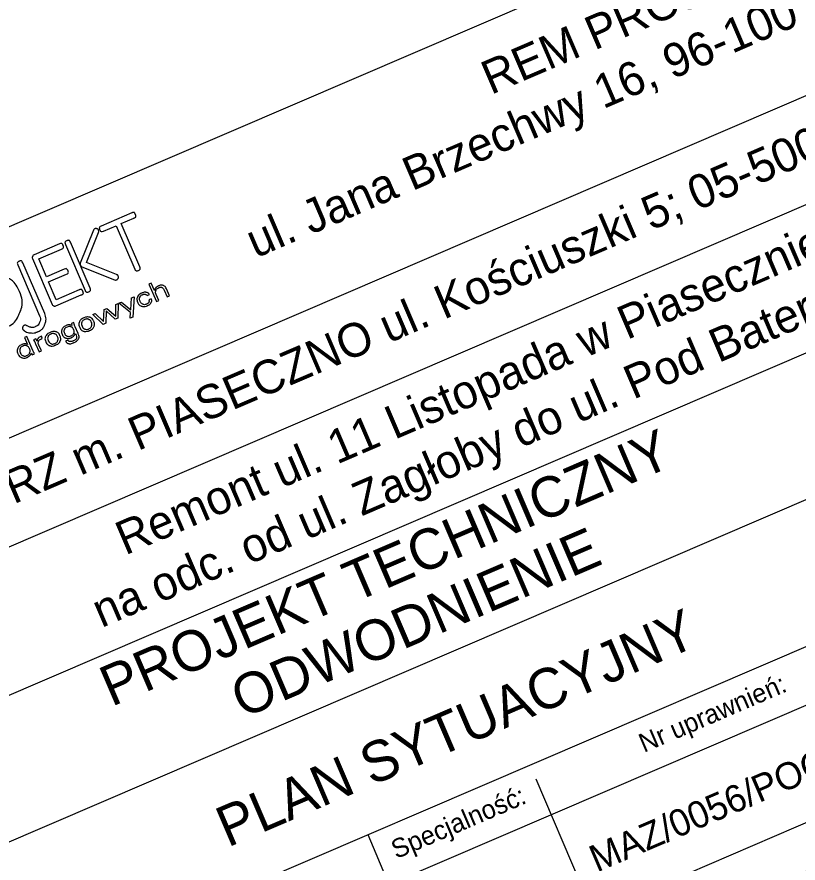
# Model space of a CAD drawing. Extents: x 7500108 to 7500715, y 5768804 to 5769157.
# Drawn here: x 7500613.89 to 7500642.87, y 5769014.08 to 5769045.44 of the extents above; entities that cross this region are included whole.
import ezdxf

# ---------------------------------------------------------------- set-up
doc = ezdxf.new("R2010")
doc.units = 0
doc.layers.add('KLASOUZYTKI', color=7, linetype='Continuous')

msp = doc.modelspace()

# ---------------------------------------------------------------- linework, layer by layer
at = {"layer": 'KLASOUZYTKI'}
for p, q in [((7500592.463, 5769020.775), (7500656.791, 5769048.376)), ((7500593.929, 5769017.358), (7500658.257, 5769044.959)), ((7500595.919, 5769012.719), (7500660.248, 5769040.32)), ((7500618.876, 5769035.575), (7500618.79, 5769035.538)), ((7500618.79, 5769035.538), (7500619.067, 5769034.893)), ((7500618.993, 5769035.302), (7500618.876, 5769035.575)), ((7500619.355, 5769035.316), (7500619.464, 5769035.063)), ((7500619.55, 5769035.1), (7500619.436, 5769035.365)), ((7500618.719, 5769035.115), (7500618.808, 5769035.154)), ((7500618.877, 5769034.993), (7500618.788, 5769034.955)), ((7500619.153, 5769034.93), (7500619.057, 5769035.154)), ((7500619.464, 5769035.063), (7500619.55, 5769035.1)), ((7500619.067, 5769034.893), (7500619.153, 5769034.93)), ((7500614.599, 5769033.509), (7500614.511, 5769033.471)), ((7500614.64, 5769033.427), (7500614.599, 5769033.509)), ((7500614.799, 5769033.607), (7500614.783, 5769033.6)), ((7500614.833, 5769033.528), (7500614.799, 5769033.607)), ((7500614.814, 5769033.52), (7500614.833, 5769033.528)), ((7500614.584, 5769033.321), (7500614.712, 5769033.024)), ((7500614.799, 5769033.062), (7500614.708, 5769033.274)), ((7500614.712, 5769033.024), (7500614.799, 5769033.062)), ((7500597.891, 5769008.124), (7500652.111, 5769031.388)), ((7500600.651, 5769001.691), (7500664.98, 5769029.292)), ((7500599.862, 5769003.529), (7500654.082, 5769026.793)), ((7500602.228, 5768998.015), (7500656.448, 5769021.279)), ((7500633.138, 5769017.202), (7500636.862, 5769008.522)), ((7500626.905, 5769015.132), (7500630.848, 5769005.942))]:
    msp.add_line(p, q, dxfattribs=at)
msp.add_lwpolyline([(7500603.806, 5768994.339), (7500668.134, 5769021.941), (7500653.956, 5769054.985), (7500589.627, 5769027.383)], close=True, dxfattribs=at)
for points in [[(7500618.152, 5769038.176), (7500617.018, 5769037.689)], [(7500618.449, 5769036.177), (7500617.76, 5769037.783), (7500618.233, 5769037.986)], [(7500616.728, 5769037.531), (7500616.243, 5769036.316)], [(7500617.1, 5769037.5), (7500617.571, 5769037.702), (7500618.26, 5769036.097)], [(7500617.591, 5769035.888), (7500616.471, 5769036.336), (7500616.919, 5769037.455)], [(7500615.47, 5769037.025), (7500614.526, 5769036.62)], [(7500615.689, 5769037.007), (7500616.419, 5769035.306)], [(7500616.607, 5769035.387), (7500615.877, 5769037.088)], [(7500615.647, 5769036.093), (7500614.985, 5769035.809), (7500614.701, 5769036.471), (7500615.551, 5769036.835)], [(7500613.922, 5769036.249), (7500614.732, 5769034.361)], [(7500614.921, 5769034.442), (7500614.111, 5769036.33)], [(7500614.472, 5769036.484), (7500615.201, 5769034.784)], [(7500615.35, 5769034.958), (7500615.066, 5769035.62), (7500615.728, 5769035.904)], [(7500616.3, 5769036.182), (7500617.515, 5769035.697)], [(7500616.201, 5769035.322), (7500615.35, 5769034.958)], [(7500615.337, 5769034.73), (7500616.28, 5769035.134)], [(7500618.185, 5769034.313), (7500618.091, 5769034.273), (7500618.105, 5769034.483), (7500617.674, 5769034.828), (7500617.775, 5769034.871), (7500618.118, 5769034.587), (7500618.145, 5769035.03), (7500618.239, 5769035.07), (7500618.185, 5769034.313)], [(7500617.539, 5769034.237), (7500617.199, 5769034.544), (7500617.185, 5769034.086), (7500617.093, 5769034.046), (7500616.702, 5769034.411), (7500616.793, 5769034.45), (7500617.106, 5769034.152), (7500617.123, 5769034.592), (7500617.228, 5769034.636), (7500617.555, 5769034.344), (7500617.565, 5769034.781), (7500617.648, 5769034.817), (7500617.637, 5769034.28), (7500617.539, 5769034.237)], [(7500615.998, 5769034.109), (7500615.912, 5769034.072), (7500615.933, 5769034.005)], [(7500616.161, 5769033.708), (7500616.055, 5769033.955), (7500616.045, 5769033.977)], [(7500614.481, 5769033.078), (7500614.26, 5769033.594), (7500614.174, 5769033.558), (7500614.285, 5769033.301)], [(7500615.785, 5769033.463), (7500615.697, 5769033.425)], [(7500616.065, 5769033.701), (7500616.089, 5769033.645)], [(7500614.421, 5769032.981), (7500614.457, 5769032.915), (7500614.544, 5769032.953)]]:
    msp.add_lwpolyline(points, dxfattribs=at)
for points, degree in [([(7500618.286, 5769038.121), (7500618.259, 5769038.184), (7500618.214, 5769038.203), (7500618.152, 5769038.176)], 2), ([(7500618.233, 5769037.986), (7500618.296, 5769038.013), (7500618.313, 5769038.058), (7500618.286, 5769038.121)], 2), ([(7500616.919, 5769037.455), (7500616.93, 5769037.483), (7500616.93, 5769037.509), (7500616.92, 5769037.534), (7500616.92, 5769037.534), (7500616.909, 5769037.559), (7500616.889, 5769037.578), (7500616.861, 5769037.589), (7500616.861, 5769037.589), (7500616.833, 5769037.6), (7500616.806, 5769037.6), (7500616.78, 5769037.589), (7500616.78, 5769037.589), (7500616.756, 5769037.578), (7500616.739, 5769037.559), (7500616.728, 5769037.531)], 3), ([(7500617.018, 5769037.689), (7500616.955, 5769037.662), (7500616.937, 5769037.617), (7500616.964, 5769037.554), (7500616.964, 5769037.554), (7500616.991, 5769037.491), (7500617.036, 5769037.473), (7500617.1, 5769037.5)], 3), ([(7500615.877, 5769037.088), (7500615.85, 5769037.151), (7500615.805, 5769037.17), (7500615.743, 5769037.143), (7500615.743, 5769037.143), (7500615.68, 5769037.116), (7500615.662, 5769037.071), (7500615.689, 5769037.007)], 3), ([(7500615.551, 5769036.835), (7500615.615, 5769036.863), (7500615.633, 5769036.908), (7500615.605, 5769036.971), (7500615.605, 5769036.971), (7500615.578, 5769037.034), (7500615.533, 5769037.052), (7500615.47, 5769037.025)], 3), ([(7500614.526, 5769036.62), (7500614.5, 5769036.609), (7500614.482, 5769036.59), (7500614.471, 5769036.563), (7500614.471, 5769036.563), (7500614.461, 5769036.536), (7500614.461, 5769036.509), (7500614.472, 5769036.484)], 3), ([(7500614.111, 5769036.33), (7500614.083, 5769036.393), (7500614.039, 5769036.412), (7500613.976, 5769036.385), (7500613.976, 5769036.385), (7500613.913, 5769036.358), (7500613.895, 5769036.313), (7500613.922, 5769036.249)], 3), ([(7500616.243, 5769036.316), (7500616.232, 5769036.291), (7500616.232, 5769036.265), (7500616.243, 5769036.238), (7500616.243, 5769036.238), (7500616.255, 5769036.21), (7500616.274, 5769036.192), (7500616.3, 5769036.182)], 3), ([(7500613.985, 5769035.269), (7500613.872, 5769035.531), (7500613.684, 5769035.714), (7500613.422, 5769035.82), (7500613.422, 5769035.82), (7500613.159, 5769035.924), (7500612.896, 5769035.921), (7500612.634, 5769035.808), (7500612.634, 5769035.808), (7500612.372, 5769035.696), (7500612.188, 5769035.508), (7500612.083, 5769035.245), (7500612.083, 5769035.245), (7500612.007, 5769035.054), (7500611.988, 5769034.864), (7500612.026, 5769034.673)], 3), ([(7500615.728, 5769035.904), (7500615.791, 5769035.931), (7500615.809, 5769035.976), (7500615.782, 5769036.039), (7500615.782, 5769036.039), (7500615.755, 5769036.102), (7500615.71, 5769036.12), (7500615.647, 5769036.093)], 3), ([(7500618.26, 5769036.097), (7500618.288, 5769036.033), (7500618.333, 5769036.015), (7500618.396, 5769036.042), (7500618.396, 5769036.042), (7500618.458, 5769036.069), (7500618.476, 5769036.114), (7500618.449, 5769036.177)], 3), ([(7500617.515, 5769035.697), (7500617.542, 5769035.686), (7500617.567, 5769035.687), (7500617.592, 5769035.697), (7500617.592, 5769035.697), (7500617.618, 5769035.708), (7500617.636, 5769035.728), (7500617.648, 5769035.755), (7500617.648, 5769035.755), (7500617.659, 5769035.783), (7500617.659, 5769035.81), (7500617.648, 5769035.836)], 3), ([(7500617.648, 5769035.836), (7500617.638, 5769035.859), (7500617.619, 5769035.877), (7500617.591, 5769035.888)], 2), ([(7500616.336, 5769035.269), (7500616.309, 5769035.332), (7500616.264, 5769035.349), (7500616.201, 5769035.322)], 2), ([(7500616.419, 5769035.306), (7500616.446, 5769035.243), (7500616.491, 5769035.225), (7500616.554, 5769035.252), (7500616.554, 5769035.252), (7500616.617, 5769035.279), (7500616.634, 5769035.324), (7500616.607, 5769035.387)], 3), ([(7500619.436, 5769035.365), (7500619.409, 5769035.429), (7500619.37, 5769035.47), (7500619.321, 5769035.488), (7500619.321, 5769035.488), (7500619.271, 5769035.506), (7500619.212, 5769035.5), (7500619.143, 5769035.47), (7500619.143, 5769035.47), (7500619.101, 5769035.452), (7500619.067, 5769035.429), (7500619.042, 5769035.401), (7500619.042, 5769035.401), (7500619.018, 5769035.373), (7500619.001, 5769035.34), (7500618.993, 5769035.302)], 3), ([(7500619.057, 5769035.154), (7500619.034, 5769035.207), (7500619.031, 5769035.256), (7500619.049, 5769035.302), (7500619.049, 5769035.302), (7500619.066, 5769035.347), (7500619.101, 5769035.381), (7500619.153, 5769035.403), (7500619.153, 5769035.403), (7500619.199, 5769035.423), (7500619.24, 5769035.426), (7500619.273, 5769035.411), (7500619.273, 5769035.411), (7500619.307, 5769035.397), (7500619.334, 5769035.365), (7500619.355, 5769035.316)], 3), ([(7500612.026, 5769034.673), (7500612.041, 5769034.601), (7500612.063, 5769034.53), (7500612.094, 5769034.458), (7500612.094, 5769034.458), (7500612.207, 5769034.194), (7500612.395, 5769034.011), (7500612.657, 5769033.906), (7500612.657, 5769033.906), (7500612.92, 5769033.801), (7500613.182, 5769033.805), (7500613.445, 5769033.918), (7500613.445, 5769033.918), (7500613.708, 5769034.031), (7500613.892, 5769034.218), (7500613.997, 5769034.481), (7500613.997, 5769034.481), (7500614.102, 5769034.743), (7500614.098, 5769035.005), (7500613.985, 5769035.269)], 3), ([(7500616.28, 5769035.134), (7500616.344, 5769035.162), (7500616.363, 5769035.207), (7500616.336, 5769035.269)], 2), ([(7500618.808, 5769035.154), (7500618.781, 5769035.195), (7500618.743, 5769035.221), (7500618.694, 5769035.23), (7500618.694, 5769035.23), (7500618.644, 5769035.24), (7500618.59, 5769035.232), (7500618.53, 5769035.206), (7500618.53, 5769035.206), (7500618.45, 5769035.172), (7500618.396, 5769035.124), (7500618.367, 5769035.062), (7500618.367, 5769035.062), (7500618.339, 5769035.001), (7500618.341, 5769034.934), (7500618.372, 5769034.861), (7500618.372, 5769034.861), (7500618.403, 5769034.788), (7500618.451, 5769034.741), (7500618.515, 5769034.719), (7500618.515, 5769034.719), (7500618.579, 5769034.698), (7500618.652, 5769034.705), (7500618.735, 5769034.74), (7500618.735, 5769034.74), (7500618.798, 5769034.768), (7500618.843, 5769034.804), (7500618.869, 5769034.85), (7500618.869, 5769034.85), (7500618.894, 5769034.896), (7500618.897, 5769034.943), (7500618.877, 5769034.993)], 3), ([(7500618.788, 5769034.955), (7500618.8, 5769034.922), (7500618.798, 5769034.891), (7500618.782, 5769034.863), (7500618.782, 5769034.863), (7500618.767, 5769034.835), (7500618.739, 5769034.812), (7500618.7, 5769034.795), (7500618.7, 5769034.795), (7500618.649, 5769034.774), (7500618.603, 5769034.772), (7500618.56, 5769034.791), (7500618.56, 5769034.791), (7500618.517, 5769034.81), (7500618.485, 5769034.846), (7500618.461, 5769034.9), (7500618.461, 5769034.9), (7500618.438, 5769034.955), (7500618.434, 5769035.004), (7500618.45, 5769035.048), (7500618.45, 5769035.048), (7500618.466, 5769035.091), (7500618.5, 5769035.124), (7500618.552, 5769035.146), (7500618.552, 5769035.146), (7500618.587, 5769035.161), (7500618.618, 5769035.166), (7500618.645, 5769035.16), (7500618.645, 5769035.16), (7500618.673, 5769035.155), (7500618.698, 5769035.14), (7500618.719, 5769035.115)], 3), ([(7500615.201, 5769034.784), (7500615.212, 5769034.759), (7500615.231, 5769034.741), (7500615.258, 5769034.73), (7500615.258, 5769034.73), (7500615.285, 5769034.719), (7500615.311, 5769034.719), (7500615.337, 5769034.73)], 3), ([(7500614.732, 5769034.361), (7500614.766, 5769034.282), (7500614.767, 5769034.204), (7500614.735, 5769034.125), (7500614.735, 5769034.125), (7500614.704, 5769034.046), (7500614.649, 5769033.99), (7500614.572, 5769033.956), (7500614.572, 5769033.956), (7500614.512, 5769033.931), (7500614.453, 5769033.925), (7500614.394, 5769033.939), (7500614.394, 5769033.939), (7500614.372, 5769033.944), (7500614.328, 5769033.962), (7500614.265, 5769033.993), (7500614.265, 5769033.993), (7500614.22, 5769034.013), (7500614.187, 5769034.019), (7500614.165, 5769034.009), (7500614.165, 5769034.009), (7500614.139, 5769033.998), (7500614.12, 5769033.979), (7500614.108, 5769033.951), (7500614.108, 5769033.951), (7500614.095, 5769033.924), (7500614.094, 5769033.898), (7500614.105, 5769033.873), (7500614.105, 5769033.873), (7500614.11, 5769033.86), (7500614.122, 5769033.846), (7500614.141, 5769033.831), (7500614.141, 5769033.831), (7500614.207, 5769033.774), (7500614.29, 5769033.741), (7500614.388, 5769033.73), (7500614.388, 5769033.73), (7500614.482, 5769033.72), (7500614.57, 5769033.733), (7500614.653, 5769033.768), (7500614.653, 5769033.768), (7500614.783, 5769033.824), (7500614.874, 5769033.917), (7500614.926, 5769034.049), (7500614.926, 5769034.049), (7500614.978, 5769034.18), (7500614.977, 5769034.311), (7500614.921, 5769034.442)], 3), ([(7500615.933, 5769034.005), (7500615.901, 5769034.021), (7500615.867, 5769034.028), (7500615.831, 5769034.028), (7500615.831, 5769034.028), (7500615.794, 5769034.027), (7500615.756, 5769034.018), (7500615.716, 5769034.001), (7500615.716, 5769034.001), (7500615.643, 5769033.969), (7500615.593, 5769033.924), (7500615.567, 5769033.864), (7500615.567, 5769033.864), (7500615.541, 5769033.805), (7500615.543, 5769033.741), (7500615.572, 5769033.673), (7500615.572, 5769033.673), (7500615.601, 5769033.606), (7500615.645, 5769033.561), (7500615.706, 5769033.539), (7500615.706, 5769033.539), (7500615.767, 5769033.517), (7500615.833, 5769033.522), (7500615.904, 5769033.552), (7500615.904, 5769033.552), (7500615.943, 5769033.569), (7500615.977, 5769033.59), (7500616.003, 5769033.615), (7500616.003, 5769033.615), (7500616.03, 5769033.639), (7500616.05, 5769033.668), (7500616.065, 5769033.701)], 3), ([(7500616.045, 5769033.977), (7500616.033, 5769034.005), (7500616.024, 5769034.029), (7500616.017, 5769034.049), (7500616.017, 5769034.049), (7500616.01, 5769034.069), (7500616.003, 5769034.089), (7500615.998, 5769034.109)], 3), ([(7500616.379, 5769034.285), (7500616.297, 5769034.25), (7500616.242, 5769034.202), (7500616.213, 5769034.141), (7500616.213, 5769034.141), (7500616.185, 5769034.08), (7500616.187, 5769034.012), (7500616.219, 5769033.937), (7500616.219, 5769033.937), (7500616.251, 5769033.863), (7500616.299, 5769033.815), (7500616.362, 5769033.793), (7500616.362, 5769033.793), (7500616.409, 5769033.778), (7500616.46, 5769033.777), (7500616.516, 5769033.791)], 3), ([(7500616.307, 5769033.975), (7500616.285, 5769034.026), (7500616.283, 5769034.075), (7500616.302, 5769034.122), (7500616.302, 5769034.122), (7500616.32, 5769034.168), (7500616.355, 5769034.202), (7500616.406, 5769034.224), (7500616.406, 5769034.224), (7500616.456, 5769034.246), (7500616.505, 5769034.248), (7500616.552, 5769034.229), (7500616.552, 5769034.229), (7500616.599, 5769034.21), (7500616.633, 5769034.175), (7500616.655, 5769034.124), (7500616.655, 5769034.124), (7500616.676, 5769034.074), (7500616.678, 5769034.025), (7500616.659, 5769033.979), (7500616.659, 5769033.979), (7500616.641, 5769033.932), (7500616.606, 5769033.898), (7500616.555, 5769033.876), (7500616.555, 5769033.876), (7500616.504, 5769033.854), (7500616.455, 5769033.852), (7500616.409, 5769033.871), (7500616.409, 5769033.871), (7500616.363, 5769033.889), (7500616.329, 5769033.924), (7500616.307, 5769033.975)], 3), ([(7500616.516, 5769033.791), (7500616.537, 5769033.797), (7500616.559, 5769033.804), (7500616.582, 5769033.814), (7500616.582, 5769033.814), (7500616.664, 5769033.849), (7500616.72, 5769033.898), (7500616.748, 5769033.959), (7500616.748, 5769033.959), (7500616.776, 5769034.02), (7500616.774, 5769034.088), (7500616.742, 5769034.162), (7500616.742, 5769034.162), (7500616.71, 5769034.236), (7500616.662, 5769034.284), (7500616.599, 5769034.306), (7500616.599, 5769034.306), (7500616.535, 5769034.328), (7500616.462, 5769034.321), (7500616.379, 5769034.285)], 3), ([(7500615.124, 5769033.747), (7500615.042, 5769033.711), (7500614.986, 5769033.663), (7500614.958, 5769033.602), (7500614.958, 5769033.602), (7500614.93, 5769033.541), (7500614.932, 5769033.473), (7500614.964, 5769033.399), (7500614.964, 5769033.399), (7500614.996, 5769033.325), (7500615.044, 5769033.276), (7500615.107, 5769033.255), (7500615.107, 5769033.255), (7500615.153, 5769033.239), (7500615.205, 5769033.238), (7500615.261, 5769033.253)], 3), ([(7500615.052, 5769033.437), (7500615.03, 5769033.488), (7500615.028, 5769033.536), (7500615.046, 5769033.583), (7500615.046, 5769033.583), (7500615.065, 5769033.63), (7500615.099, 5769033.664), (7500615.15, 5769033.686), (7500615.15, 5769033.686), (7500615.201, 5769033.707), (7500615.25, 5769033.709), (7500615.297, 5769033.69), (7500615.297, 5769033.69), (7500615.343, 5769033.672), (7500615.378, 5769033.637), (7500615.399, 5769033.586), (7500615.399, 5769033.586), (7500615.421, 5769033.535), (7500615.423, 5769033.486), (7500615.404, 5769033.44), (7500615.404, 5769033.44), (7500615.386, 5769033.394), (7500615.351, 5769033.359), (7500615.3, 5769033.337), (7500615.3, 5769033.337), (7500615.249, 5769033.316), (7500615.2, 5769033.314), (7500615.154, 5769033.332), (7500615.154, 5769033.332), (7500615.108, 5769033.351), (7500615.074, 5769033.386), (7500615.052, 5769033.437)], 3), ([(7500615.261, 5769033.253), (7500615.282, 5769033.258), (7500615.304, 5769033.266), (7500615.327, 5769033.275), (7500615.327, 5769033.275), (7500615.409, 5769033.311), (7500615.464, 5769033.359), (7500615.493, 5769033.42), (7500615.493, 5769033.42), (7500615.521, 5769033.481), (7500615.519, 5769033.549), (7500615.487, 5769033.623), (7500615.487, 5769033.623), (7500615.455, 5769033.698), (7500615.407, 5769033.746), (7500615.344, 5769033.767), (7500615.344, 5769033.767), (7500615.28, 5769033.789), (7500615.207, 5769033.782), (7500615.124, 5769033.747)], 3), ([(7500615.755, 5769033.947), (7500615.806, 5769033.969), (7500615.853, 5769033.972), (7500615.897, 5769033.956), (7500615.897, 5769033.956), (7500615.941, 5769033.94), (7500615.973, 5769033.908), (7500615.993, 5769033.86), (7500615.993, 5769033.86), (7500616.016, 5769033.807), (7500616.019, 5769033.76), (7500616.001, 5769033.717), (7500616.001, 5769033.717), (7500615.984, 5769033.675), (7500615.949, 5769033.642), (7500615.896, 5769033.62), (7500615.896, 5769033.62), (7500615.845, 5769033.598), (7500615.798, 5769033.595), (7500615.756, 5769033.611), (7500615.756, 5769033.611), (7500615.714, 5769033.627), (7500615.681, 5769033.66), (7500615.66, 5769033.711), (7500615.66, 5769033.711), (7500615.637, 5769033.763), (7500615.634, 5769033.81), (7500615.651, 5769033.852), (7500615.651, 5769033.852), (7500615.668, 5769033.893), (7500615.702, 5769033.925), (7500615.755, 5769033.947)], 3), ([(7500615.697, 5769033.425), (7500615.72, 5769033.374), (7500615.756, 5769033.343), (7500615.807, 5769033.332), (7500615.807, 5769033.332), (7500615.857, 5769033.322), (7500615.919, 5769033.332), (7500615.992, 5769033.364), (7500615.992, 5769033.364), (7500616.048, 5769033.388), (7500616.092, 5769033.414), (7500616.125, 5769033.443), (7500616.125, 5769033.443), (7500616.158, 5769033.472), (7500616.18, 5769033.504), (7500616.191, 5769033.539), (7500616.191, 5769033.539), (7500616.197, 5769033.559), (7500616.199, 5769033.581), (7500616.195, 5769033.604), (7500616.195, 5769033.604), (7500616.192, 5769033.628), (7500616.18, 5769033.662), (7500616.161, 5769033.708)], 3), ([(7500614.511, 5769033.471), (7500614.525, 5769033.445), (7500614.538, 5769033.419), (7500614.551, 5769033.394), (7500614.551, 5769033.394), (7500614.563, 5769033.369), (7500614.574, 5769033.345), (7500614.584, 5769033.321)], 3), ([(7500614.783, 5769033.6), (7500614.736, 5769033.58), (7500614.701, 5769033.556), (7500614.678, 5769033.528), (7500614.678, 5769033.528), (7500614.655, 5769033.499), (7500614.642, 5769033.466), (7500614.64, 5769033.427)], 3), ([(7500614.708, 5769033.274), (7500614.683, 5769033.333), (7500614.679, 5769033.382), (7500614.696, 5769033.421), (7500614.696, 5769033.421), (7500614.713, 5769033.461), (7500614.752, 5769033.494), (7500614.814, 5769033.52)], 3), ([(7500616.089, 5769033.645), (7500616.109, 5769033.597), (7500616.111, 5769033.556), (7500616.093, 5769033.521), (7500616.093, 5769033.521), (7500616.075, 5769033.487), (7500616.037, 5769033.457), (7500615.979, 5769033.432), (7500615.979, 5769033.432), (7500615.929, 5769033.41), (7500615.888, 5769033.402), (7500615.856, 5769033.407), (7500615.856, 5769033.407), (7500615.825, 5769033.412), (7500615.801, 5769033.43), (7500615.785, 5769033.463)], 3), ([(7500614.285, 5769033.301), (7500614.249, 5769033.314), (7500614.213, 5769033.321), (7500614.178, 5769033.32), (7500614.178, 5769033.32), (7500614.143, 5769033.319), (7500614.106, 5769033.31), (7500614.07, 5769033.294), (7500614.07, 5769033.294), (7500613.996, 5769033.263), (7500613.947, 5769033.216), (7500613.921, 5769033.155), (7500613.921, 5769033.155), (7500613.895, 5769033.093), (7500613.897, 5769033.027), (7500613.928, 5769032.955), (7500613.928, 5769032.955), (7500613.959, 5769032.883), (7500614.005, 5769032.835), (7500614.067, 5769032.811), (7500614.067, 5769032.811), (7500614.129, 5769032.787), (7500614.196, 5769032.79), (7500614.27, 5769032.822), (7500614.27, 5769032.822), (7500614.309, 5769032.839), (7500614.342, 5769032.861), (7500614.367, 5769032.887), (7500614.367, 5769032.887), (7500614.392, 5769032.913), (7500614.41, 5769032.945), (7500614.421, 5769032.981)], 3), ([(7500614.017, 5769032.992), (7500613.994, 5769033.047), (7500613.99, 5769033.097), (7500614.007, 5769033.141), (7500614.007, 5769033.141), (7500614.024, 5769033.185), (7500614.059, 5769033.218), (7500614.112, 5769033.241), (7500614.112, 5769033.241), (7500614.166, 5769033.264), (7500614.215, 5769033.267), (7500614.259, 5769033.249), (7500614.259, 5769033.249), (7500614.304, 5769033.23), (7500614.337, 5769033.193), (7500614.361, 5769033.137), (7500614.361, 5769033.137), (7500614.383, 5769033.086), (7500614.385, 5769033.038), (7500614.367, 5769032.993), (7500614.367, 5769032.993), (7500614.348, 5769032.948), (7500614.313, 5769032.914), (7500614.261, 5769032.892), (7500614.261, 5769032.892), (7500614.208, 5769032.869), (7500614.16, 5769032.866), (7500614.117, 5769032.884), (7500614.117, 5769032.884), (7500614.074, 5769032.902), (7500614.041, 5769032.938), (7500614.017, 5769032.992)], 3), ([(7500614.544, 5769032.953), (7500614.534, 5769032.97), (7500614.524, 5769032.988), (7500614.514, 5769033.008), (7500614.514, 5769033.008), (7500614.504, 5769033.027), (7500614.493, 5769033.051), (7500614.481, 5769033.078)], 3)]:
    msp.add_open_spline(points, degree=degree, dxfattribs=at)

# ---------------------------------------------------------------- texts
for s, height, p in [('ul. Jana Brzechwy 16, 96-100 Skierniewice', 1.25, (7500622.743, 5769036.486)), ('REM PROJEKT', 1.25, (7500631.475, 5769042.545)), ('BURMISTRZ m. PIASECZNO ul. Kościuszki 5; 05-500 Piaseczno', 1.25, (7500606.854, 5769024.402)), ('Remont ul. 11 Listopada w Piasecznie', 1.25, (7500617.906, 5769025.475)), ('na odc. od ul. Zagłoby do ul. Pod Bateriami', 1.25, (7500617.027, 5769022.786)), ('PROJEKT TECHNICZNY', 1.5, (7500617.4, 5769019.862)), ('ODWODNIENIE', 1.5, (7500622.264, 5769019.429)), ('PLAN SYTUACYJNY', 1.5, (7500621.713, 5769014.648)), ('Nr uprawnień:', 0.7, (7500637.151, 5769018.162)), ('MAZ/0056/POOS/12', 1, (7500635.406, 5769013.723)), ('Specjalność:', 0.7, (7500627.965, 5769014.223)), ('MAZ/0240/POOS/11', 1, (7500637.064, 5769010.09))]:
    msp.add_text(s, height=height, rotation=23.2227, dxfattribs=at).set_placement(p)

doc.saveas('drawing.dxf')
